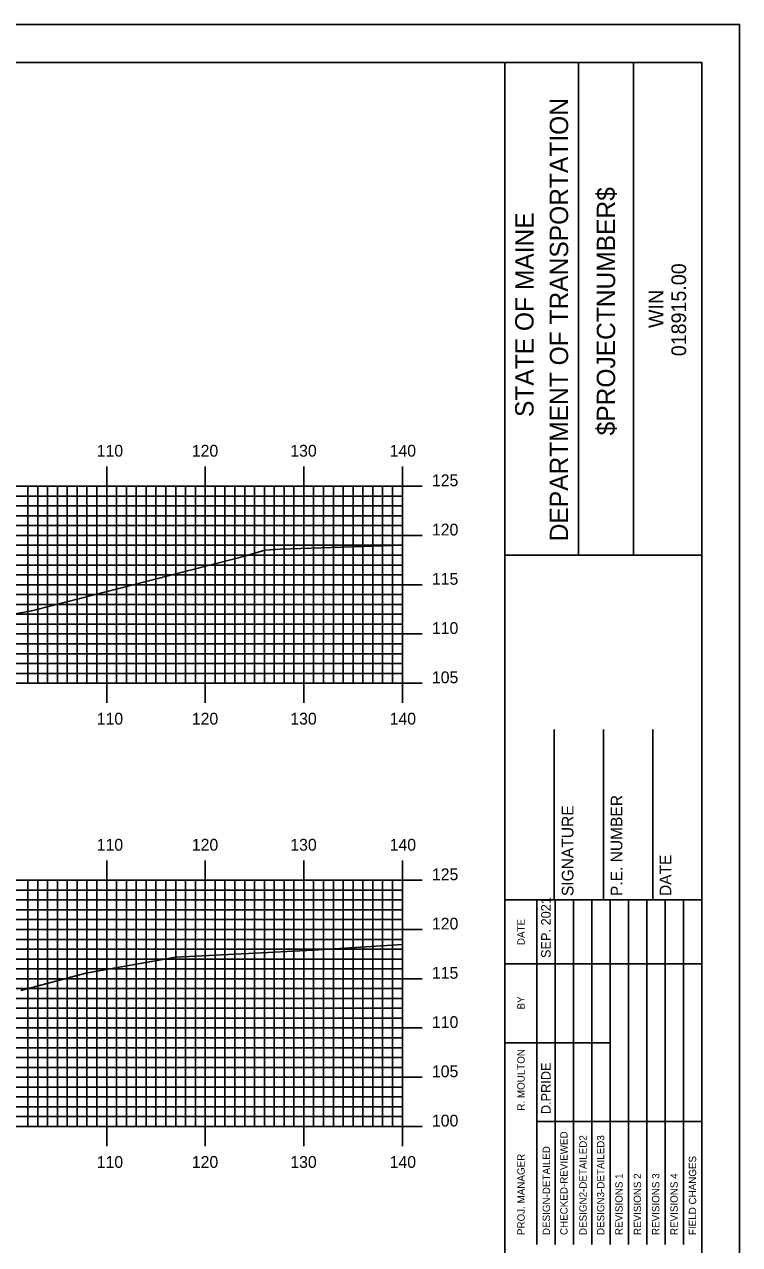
# Model space of a CAD drawing. Extents: x 1685586 to 1685929, y 461260 to 461480.
# Drawn here: x 1685853.4 to 1685926, y 461356.1 to 461480 of the extents above; entities that cross this region are included whole.
import ezdxf

# ---------------------------------------------------------------- set-up
doc = ezdxf.new("R2010")
doc.units = 0
for name, color, linetype in [('BORDER', 7, 'Continuous'), ('H_V ANNOTATION', 7, 'Continuous'), ('MAJOR', 7, 'Continuous'), ('MINOR', 7, 'Continuous'), ('PLOT BOUNDARY', 7, 'Continuous'), ('S_Roadway_Centerline', 7, 'Continuous')]:
    doc.layers.add(name, color=color, linetype=linetype)

msp = doc.modelspace()

# ---------------------------------------------------------------- linework, layer by layer
at = {"layer": 'BORDER'}
for p, q in [((1685902.14, 461266.07), (1685902.14, 461476.07)), ((1685909.6, 461426.07), (1685909.6, 461476.07)), ((1685915.19, 461426.07), (1685915.19, 461476.07)), ((1685902.14, 461426.06), (1685922.14, 461426.06)), ((1685907.14, 461391.08), (1685907.14, 461408.37)), ((1685912.14, 461391.08), (1685912.14, 461408.37)), ((1685917.14, 461391.08), (1685917.14, 461408.37)), ((1685902.14, 461391.08), (1685922.14, 461391.08))]:
    msp.add_line(p, q, dxfattribs=at)
msp.add_lwpolyline([(1685602.14, 461266.07), (1685922.14, 461266.07), (1685922.14, 461476.07), (1685602.14, 461476.07)], close=True, dxfattribs=at)
for points in [[(1685905.37, 461384.58), (1685905.37, 461391.08)], [(1685907.24, 461356.08), (1685907.24, 461391.08)], [(1685909.1, 461391.08), (1685909.1, 461356.08)], [(1685910.96, 461356.08), (1685910.96, 461391.08)], [(1685912.83, 461356.08), (1685912.83, 461391.08)], [(1685914.69, 461356.08), (1685914.69, 461391.08)], [(1685916.55, 461356.08), (1685916.55, 461391.08)], [(1685918.42, 461356.08), (1685918.42, 461391.08)], [(1685920.28, 461356.08), (1685920.28, 461391.08)], [(1685905.37, 461356.08), (1685905.37, 461389.67)], [(1685902.14, 461384.58), (1685922.14, 461384.58)], [(1685902.14, 461376.58), (1685905.37, 461376.58)], [(1685905.37, 461376.58), (1685912.83, 461376.58)], [(1685905.37, 461368.58), (1685922.14, 461368.58)]]:
    msp.add_lwpolyline(points, dxfattribs=at)
at = {"layer": 'MAJOR'}
for p, q in [((1685861.74, 461435.08), (1685861.74, 461433.07)), ((1685871.74, 461435.08), (1685871.74, 461433.07)), ((1685881.74, 461435.08), (1685881.74, 461433.07)), ((1685891.74, 461435.08), (1685891.74, 461433.07)), ((1685611.74, 461433.07), (1685891.74, 461433.07)), ((1685611.74, 461433.07), (1685891.74, 461433.07)), ((1685861.74, 461413.07), (1685861.74, 461433.07)), ((1685871.74, 461413.07), (1685871.74, 461433.07)), ((1685881.74, 461413.07), (1685881.74, 461433.07)), ((1685893.75, 461433.07), (1685889.74, 461433.07)), ((1685891.74, 461413.07), (1685891.74, 461433.07)), ((1685891.74, 461413.07), (1685891.74, 461433.07)), ((1685611.74, 461428.07), (1685891.74, 461428.07)), ((1685893.75, 461428.07), (1685889.74, 461428.07)), ((1685611.74, 461423.07), (1685891.74, 461423.07)), ((1685893.75, 461423.07), (1685889.74, 461423.07)), ((1685611.74, 461418.07), (1685891.74, 461418.07)), ((1685893.75, 461418.07), (1685889.74, 461418.07)), ((1685611.74, 461413.07), (1685891.74, 461413.07)), ((1685611.74, 461413.07), (1685891.74, 461413.07)), ((1685861.74, 461411.07), (1685861.74, 461413.07)), ((1685871.74, 461411.07), (1685871.74, 461413.07)), ((1685881.74, 461411.07), (1685881.74, 461413.07)), ((1685893.75, 461413.07), (1685889.74, 461413.07)), ((1685891.74, 461411.07), (1685891.74, 461413.07)), ((1685861.74, 461395.08), (1685861.74, 461393.07)), ((1685871.74, 461395.08), (1685871.74, 461393.07)), ((1685881.74, 461395.08), (1685881.74, 461393.07)), ((1685891.74, 461395.08), (1685891.74, 461393.07)), ((1685611.74, 461393.07), (1685891.74, 461393.07)), ((1685611.74, 461393.07), (1685891.74, 461393.07)), ((1685861.74, 461368.07), (1685861.74, 461393.07)), ((1685871.74, 461368.07), (1685871.74, 461393.07)), ((1685881.74, 461368.07), (1685881.74, 461393.07)), ((1685893.75, 461393.07), (1685889.74, 461393.07)), ((1685891.74, 461368.07), (1685891.74, 461393.07)), ((1685891.74, 461368.07), (1685891.74, 461393.07)), ((1685611.74, 461388.07), (1685891.74, 461388.07)), ((1685893.75, 461388.07), (1685889.74, 461388.07)), ((1685611.74, 461383.07), (1685891.74, 461383.07)), ((1685893.75, 461383.07), (1685889.74, 461383.07)), ((1685611.74, 461378.07), (1685891.74, 461378.07)), ((1685893.75, 461378.07), (1685889.74, 461378.07)), ((1685611.74, 461373.07), (1685891.74, 461373.07)), ((1685893.75, 461373.07), (1685889.74, 461373.07)), ((1685611.74, 461368.07), (1685891.74, 461368.07)), ((1685611.74, 461368.07), (1685891.74, 461368.07)), ((1685861.74, 461366.07), (1685861.74, 461368.07)), ((1685871.74, 461366.07), (1685871.74, 461368.07)), ((1685881.74, 461366.07), (1685881.74, 461368.07)), ((1685893.75, 461368.07), (1685889.74, 461368.07)), ((1685891.74, 461366.07), (1685891.74, 461368.07))]:
    msp.add_line(p, q, dxfattribs=at)
at = {"layer": 'MINOR'}
for p, q in [((1685853.74, 461413.07), (1685853.74, 461433.07)), ((1685854.74, 461413.07), (1685854.74, 461433.07)), ((1685855.74, 461413.07), (1685855.74, 461433.07)), ((1685856.74, 461413.07), (1685856.74, 461433.07)), ((1685857.74, 461413.07), (1685857.74, 461433.07)), ((1685858.74, 461413.07), (1685858.74, 461433.07)), ((1685859.74, 461413.07), (1685859.74, 461433.07)), ((1685860.74, 461413.07), (1685860.74, 461433.07)), ((1685862.74, 461413.07), (1685862.74, 461433.07)), ((1685863.74, 461413.07), (1685863.74, 461433.07)), ((1685864.74, 461413.07), (1685864.74, 461433.07)), ((1685865.74, 461413.07), (1685865.74, 461433.07)), ((1685866.74, 461413.07), (1685866.74, 461433.07)), ((1685867.74, 461413.07), (1685867.74, 461433.07)), ((1685868.74, 461413.07), (1685868.74, 461433.07)), ((1685869.74, 461413.07), (1685869.74, 461433.07)), ((1685870.74, 461413.07), (1685870.74, 461433.07)), ((1685872.74, 461413.07), (1685872.74, 461433.07)), ((1685873.74, 461413.07), (1685873.74, 461433.07)), ((1685874.74, 461413.07), (1685874.74, 461433.07)), ((1685875.74, 461413.07), (1685875.74, 461433.07)), ((1685876.74, 461413.07), (1685876.74, 461433.07)), ((1685877.74, 461413.07), (1685877.74, 461433.07)), ((1685878.74, 461413.07), (1685878.74, 461433.07)), ((1685879.74, 461413.07), (1685879.74, 461433.07)), ((1685880.74, 461413.07), (1685880.74, 461433.07)), ((1685882.74, 461413.07), (1685882.74, 461433.07)), ((1685883.74, 461413.07), (1685883.74, 461433.07)), ((1685884.74, 461413.07), (1685884.74, 461433.07)), ((1685885.74, 461413.07), (1685885.74, 461433.07)), ((1685886.74, 461413.07), (1685886.74, 461433.07)), ((1685887.74, 461413.07), (1685887.74, 461433.07)), ((1685888.74, 461413.07), (1685888.74, 461433.07)), ((1685889.74, 461413.07), (1685889.74, 461433.07)), ((1685890.74, 461413.07), (1685890.74, 461433.07)), ((1685611.74, 461432.07), (1685891.74, 461432.07)), ((1685891.74, 461432.07), (1685889.74, 461432.07)), ((1685611.74, 461431.07), (1685891.74, 461431.07)), ((1685611.74, 461430.07), (1685891.74, 461430.07)), ((1685891.74, 461431.07), (1685889.74, 461431.07)), ((1685891.74, 461430.07), (1685889.74, 461430.07)), ((1685611.74, 461429.07), (1685891.74, 461429.07)), ((1685891.74, 461429.07), (1685889.74, 461429.07)), ((1685611.74, 461427.07), (1685891.74, 461427.07)), ((1685891.74, 461427.07), (1685889.74, 461427.07)), ((1685611.74, 461426.07), (1685891.74, 461426.07)), ((1685611.74, 461425.07), (1685891.74, 461425.07)), ((1685891.74, 461426.07), (1685889.74, 461426.07)), ((1685891.74, 461425.07), (1685889.74, 461425.07)), ((1685611.74, 461424.07), (1685891.74, 461424.07)), ((1685891.74, 461424.07), (1685889.74, 461424.07)), ((1685611.74, 461422.07), (1685891.74, 461422.07)), ((1685891.74, 461422.07), (1685889.74, 461422.07)), ((1685611.74, 461421.07), (1685891.74, 461421.07)), ((1685611.74, 461420.07), (1685891.74, 461420.07)), ((1685891.74, 461421.07), (1685889.74, 461421.07)), ((1685891.74, 461420.07), (1685889.74, 461420.07)), ((1685611.74, 461419.07), (1685891.74, 461419.07)), ((1685891.74, 461419.07), (1685889.74, 461419.07)), ((1685611.74, 461417.07), (1685891.74, 461417.07)), ((1685891.74, 461417.07), (1685889.74, 461417.07)), ((1685611.74, 461416.07), (1685891.74, 461416.07)), ((1685891.74, 461416.07), (1685889.74, 461416.07)), ((1685611.74, 461415.07), (1685891.74, 461415.07)), ((1685611.74, 461414.07), (1685891.74, 461414.07)), ((1685891.74, 461415.07), (1685889.74, 461415.07)), ((1685891.74, 461414.07), (1685889.74, 461414.07)), ((1685853.74, 461368.07), (1685853.74, 461393.07)), ((1685854.74, 461368.07), (1685854.74, 461393.07)), ((1685855.74, 461368.07), (1685855.74, 461393.07)), ((1685856.74, 461368.07), (1685856.74, 461393.07)), ((1685857.74, 461368.07), (1685857.74, 461393.07)), ((1685858.74, 461368.07), (1685858.74, 461393.07)), ((1685859.74, 461368.07), (1685859.74, 461393.07)), ((1685860.74, 461368.07), (1685860.74, 461393.07)), ((1685862.74, 461368.07), (1685862.74, 461393.07)), ((1685863.74, 461368.07), (1685863.74, 461393.07)), ((1685864.74, 461368.07), (1685864.74, 461393.07)), ((1685865.74, 461368.07), (1685865.74, 461393.07)), ((1685866.74, 461368.07), (1685866.74, 461393.07)), ((1685867.74, 461368.07), (1685867.74, 461393.07)), ((1685868.74, 461368.07), (1685868.74, 461393.07)), ((1685869.74, 461368.07), (1685869.74, 461393.07)), ((1685870.74, 461368.07), (1685870.74, 461393.07)), ((1685872.74, 461368.07), (1685872.74, 461393.07)), ((1685873.74, 461368.07), (1685873.74, 461393.07)), ((1685874.74, 461368.07), (1685874.74, 461393.07)), ((1685875.74, 461368.07), (1685875.74, 461393.07)), ((1685876.74, 461368.07), (1685876.74, 461393.07)), ((1685877.74, 461368.07), (1685877.74, 461393.07)), ((1685878.74, 461368.07), (1685878.74, 461393.07)), ((1685879.74, 461368.07), (1685879.74, 461393.07)), ((1685880.74, 461368.07), (1685880.74, 461393.07)), ((1685882.74, 461368.07), (1685882.74, 461393.07)), ((1685883.74, 461368.07), (1685883.74, 461393.07)), ((1685884.74, 461368.07), (1685884.74, 461393.07)), ((1685885.74, 461368.07), (1685885.74, 461393.07)), ((1685886.74, 461368.07), (1685886.74, 461393.07)), ((1685887.74, 461368.07), (1685887.74, 461393.07)), ((1685888.74, 461368.07), (1685888.74, 461393.07)), ((1685889.74, 461368.07), (1685889.74, 461393.07)), ((1685890.74, 461368.07), (1685890.74, 461393.07)), ((1685611.74, 461392.07), (1685891.74, 461392.07)), ((1685891.74, 461392.07), (1685889.74, 461392.07)), ((1685611.74, 461391.07), (1685891.74, 461391.07)), ((1685891.74, 461391.07), (1685889.74, 461391.07)), ((1685611.74, 461390.07), (1685891.74, 461390.07)), ((1685611.74, 461389.07), (1685891.74, 461389.07)), ((1685891.74, 461390.07), (1685889.74, 461390.07)), ((1685891.74, 461389.07), (1685889.74, 461389.07)), ((1685611.74, 461387.07), (1685891.74, 461387.07)), ((1685891.74, 461387.07), (1685889.74, 461387.07)), ((1685611.74, 461386.07), (1685891.74, 461386.07)), ((1685891.74, 461386.07), (1685889.74, 461386.07)), ((1685611.74, 461385.07), (1685891.74, 461385.07)), ((1685891.74, 461385.07), (1685889.74, 461385.07)), ((1685611.74, 461384.07), (1685891.74, 461384.07)), ((1685891.74, 461384.07), (1685889.74, 461384.07)), ((1685611.74, 461382.07), (1685891.74, 461382.07)), ((1685891.74, 461382.07), (1685889.74, 461382.07)), ((1685611.74, 461381.07), (1685891.74, 461381.07)), ((1685891.74, 461381.07), (1685889.74, 461381.07)), ((1685611.74, 461380.07), (1685891.74, 461380.07)), ((1685891.74, 461380.07), (1685889.74, 461380.07)), ((1685611.74, 461379.07), (1685891.74, 461379.07)), ((1685891.74, 461379.07), (1685889.74, 461379.07)), ((1685611.74, 461377.07), (1685891.74, 461377.07)), ((1685891.74, 461377.07), (1685889.74, 461377.07)), ((1685611.74, 461376.07), (1685891.74, 461376.07)), ((1685891.74, 461376.07), (1685889.74, 461376.07)), ((1685611.74, 461375.07), (1685891.74, 461375.07)), ((1685891.74, 461375.07), (1685889.74, 461375.07)), ((1685611.74, 461374.07), (1685891.74, 461374.07)), ((1685891.74, 461374.07), (1685889.74, 461374.07)), ((1685611.74, 461372.07), (1685891.74, 461372.07)), ((1685891.74, 461372.07), (1685889.74, 461372.07)), ((1685611.74, 461371.07), (1685891.74, 461371.07)), ((1685891.74, 461371.07), (1685889.74, 461371.07)), ((1685611.74, 461370.07), (1685891.74, 461370.07)), ((1685891.74, 461370.07), (1685889.74, 461370.07)), ((1685611.74, 461369.07), (1685891.74, 461369.07)), ((1685891.74, 461369.07), (1685889.74, 461369.07))]:
    msp.add_line(p, q, dxfattribs=at)
at = {"layer": 'PLOT BOUNDARY'}
msp.add_lwpolyline([(1685585.96, 461259.95), (1685925.96, 461259.95), (1685925.96, 461479.95), (1685585.96, 461479.95)], close=True, dxfattribs=at)
at = {"layer": 'S_Roadway_Centerline'}
for points in [[(1685850.63, 461419.79), (1685854.12, 461420.41), (1685856.38, 461420.98), (1685875.75, 461425.97), (1685877.79, 461426.57), (1685879.39, 461426.69), (1685891.74, 461427.1)], [(1685853.04, 461381.89), (1685859.63, 461383.63), (1685868.76, 461385.26), (1685878.13, 461385.73), (1685880.66, 461385.87), (1685882.71, 461385.98), (1685891.74, 461386.53)]]:
    msp.add_lwpolyline(points, dxfattribs=at)

# ---------------------------------------------------------------- texts
at = {"layer": 'BORDER'}
for s, height, p in [('DEPARTMENT OF TRANSPORTATION', 1.8635, (1685908.56, 461427.48)), ('$PROJECTNUMBER$', 1.8635, (1685913.33, 461438.23)), ('STATE OF MAINE', 1.8635, (1685905.05, 461440.1)), ('018915.00', 1.491, (1685920.53, 461446.27)), ('WIN', 1.491, (1685918.22, 461449.13)), ('P.E. NUMBER', 1.1811, (1685914.06, 461391.46)), ('SIGNATURE', 1.181, (1685909.1, 461391.46)), ('DATE', 1.181, (1685919.02, 461391.46)), ('SEP. 2021', 0.969, (1685906.79, 461385.17)), ('DATE', 0.743, (1685904.15, 461386.49)), ('BY', 0.743, (1685904.15, 461379.95)), ('R. MOULTON', 0.745, (1685904.15, 461369.68)), ('D.PRIDE', 0.969, (1685906.79, 461369.32)), ('CHECKED-REVIEWED', 0.7455, (1685908.5, 461357.05)), ('DESIGN2-DETAILED2', 0.7455, (1685910.44, 461357.05)), ('DESIGN3-DETAILED3', 0.7455, (1685912.23, 461357.05)), ('DESIGN-DETAILED', 0.7455, (1685906.72, 461357.05)), ('PROJ. MANAGER', 0.7455, (1685904.15, 461357.05)), ('FIELD CHANGES', 0.7455, (1685921.55, 461357.05)), ('REVISIONS 1', 0.7455, (1685914.09, 461357.05)), ('REVISIONS 2', 0.7455, (1685915.96, 461357.05)), ('REVISIONS 3', 0.7455, (1685917.82, 461357.05)), ('REVISIONS 4', 0.7455, (1685919.68, 461357.05))]:
    msp.add_text(s, height=height, rotation=90, dxfattribs=at).set_placement(p)
at = {"layer": 'H_V ANNOTATION'}
for s, p in [('110', (1685860.73, 461436.07)), ('120', (1685870.38, 461436.07)), ('130', (1685880.37, 461436.07)), ('140', (1685890.45, 461436.07)), ('125', (1685894.74, 461433.07)), ('120', (1685894.74, 461428.07)), ('115', (1685894.74, 461423.07)), ('110', (1685894.74, 461418.07)), ('105', (1685894.74, 461413.07)), ('110', (1685860.73, 461408.87)), ('120', (1685870.38, 461408.87)), ('130', (1685880.37, 461408.87)), ('140', (1685890.45, 461408.87)), ('110', (1685860.73, 461396.07)), ('120', (1685870.38, 461396.07)), ('130', (1685880.37, 461396.07)), ('140', (1685890.45, 461396.07)), ('125', (1685894.74, 461393.07)), ('120', (1685894.74, 461388.07)), ('115', (1685894.74, 461383.07)), ('110', (1685894.74, 461378.07)), ('105', (1685894.74, 461373.07)), ('100', (1685894.74, 461368.07)), ('110', (1685860.73, 461363.87)), ('120', (1685870.38, 461363.87)), ('130', (1685880.37, 461363.87)), ('140', (1685890.45, 461363.87))]:
    msp.add_text(s, height=1.2, dxfattribs=at).set_placement(p)

doc.saveas('drawing.dxf')
